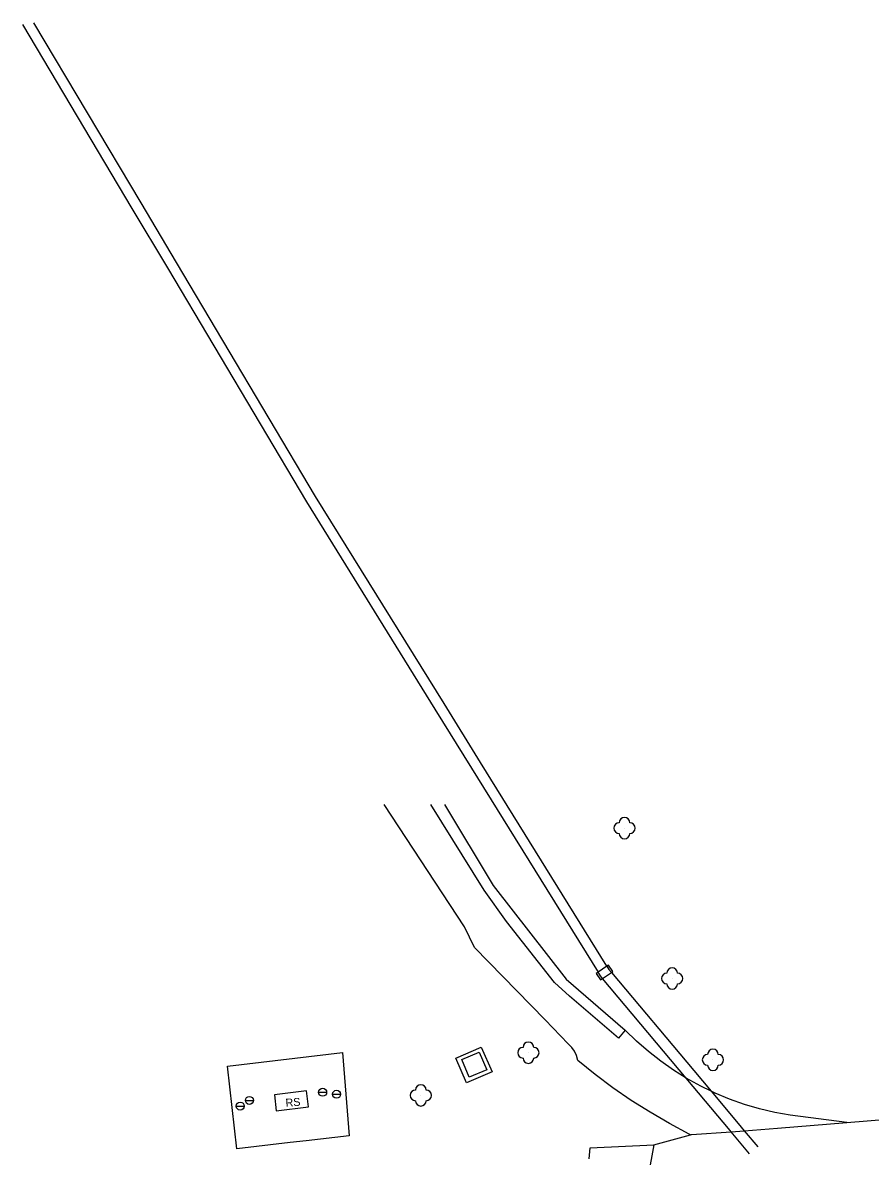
# Model space of a CAD drawing. Extents: x -536391 to -535419, y -1201788 to -1200779.
# Drawn here: x -535812.4 to -535733, y -1201615.3 to -1201509 of the extents above; entities that cross this region are included whole.
import ezdxf

# ---------------------------------------------------------------- set-up
doc = ezdxf.new("R2010")
doc.units = 0
for name, color, linetype in [('CIZÍ_PODZEM_POPIS', 7, 'Continuous'), ('KONEC_VEDENÍ', 7, 'Continuous'), ('POL_ZNAČKA_PRACOVNÍ', 7, 'Continuous'), ('SDEL_EON_POPIS', 7, 'Continuous'), ('TECH_OCHR_PÁSMO_HRAN', 7, 'Continuous')]:
    doc.layers.add(name, color=color, linetype=linetype)

msp = doc.modelspace()

# ---------------------------------------------------------------- linework, layer by layer
at = {"layer": 'CIZÍ_PODZEM_POPIS'}
for p, q in [((-535791.555, -1201610.03), (-535790.805, -1201610.03)), ((-535784.685, -1201609.27), (-535783.935, -1201609.27)), ((-535783.385, -1201609.45), (-535782.635, -1201609.45)), ((-535792.415, -1201610.57), (-535791.665, -1201610.57))]:
    msp.add_line(p, q, dxfattribs=at)
for points in [[(-535792.37, -1201614.57), (-535793.23, -1201606.83), (-535782.45, -1201605.55), (-535781.81, -1201613.35), (-535785.86, -1201613.82), (-535787.35, -1201613.99), (-535792.37, -1201614.57)], [(-535770.81, -1201608.39), (-535771.82, -1201606.08), (-535769.45, -1201605.05), (-535768.43, -1201607.36), (-535770.81, -1201608.39)]]:
    msp.add_lwpolyline(points, dxfattribs=at)
for centre in [(-535784.31, -1201609.27), (-535783.01, -1201609.45), (-535791.18, -1201610.03), (-535792.04, -1201610.57)]:
    msp.add_circle(centre, 0.375, dxfattribs=at)
at = {"layer": 'KONEC_VEDENÍ'}
for centre in [(-535756.01, -1201584.51), (-535751.54, -1201598.61), (-535765.02, -1201605.56), (-535747.71, -1201606.23), (-535775.11, -1201609.56)]:
    msp.add_circle(centre, 0.0005, dxfattribs=at)
for centre, start, end in [((-535756.01, -1201584.01), 0, 179.99999), ((-535756.51, -1201584.51), 89.99999, 269.99999), ((-535755.51, -1201584.51), 270, 89.99999), ((-535756.01, -1201585.01), 179.99999, 359.99999), ((-535752.04, -1201598.61), 89.99999, 269.99999), ((-535751.54, -1201598.11), 0, 179.99999), ((-535751.04, -1201598.61), 270, 89.99999), ((-535751.54, -1201599.11), 179.99999, 359.99999), ((-535765.02, -1201605.06), 0, 179.99999), ((-535765.52, -1201605.56), 89.99999, 269.99999), ((-535764.52, -1201605.56), 270, 89.99999), ((-535748.21, -1201606.23), 89.99999, 269.99999), ((-535747.71, -1201605.73), 0, 179.99999), ((-535747.21, -1201606.23), 270, 89.99999), ((-535765.02, -1201606.06), 179.99999, 359.99999), ((-535747.71, -1201606.73), 179.99999, 359.99999), ((-535775.61, -1201609.56), 89.99999, 269.99999), ((-535775.11, -1201609.06), 0, 179.99999), ((-535774.61, -1201609.56), 270, 89.99999), ((-535775.11, -1201610.06), 179.99999, 359.99999)]:
    msp.add_arc(centre, 0.5, start, end, dxfattribs=at)
at = {"layer": 'SDEL_EON_POPIS'}
msp.add_lwpolyline([(-535785.81, -1201609.15), (-535788.84, -1201609.5), (-535788.67, -1201611), (-535785.63, -1201610.64), (-535785.81, -1201609.15)], dxfattribs=at)
at = {"layer": 'TECH_OCHR_PÁSMO_HRAN'}
for points in [[(-535812.44, -1201509.2), (-535802.19, -1201526.43), (-535798.87, -1201532.01), (-535785.84, -1201553.94), (-535773.78, -1201573.37), (-535770.35, -1201578.89), (-535758.48, -1201598.01)], [(-535757.65, -1201597.46), (-535769.5, -1201578.36), (-535772.93, -1201572.84), (-535784.98, -1201553.42), (-535798.01, -1201531.5), (-535801.33, -1201525.92), (-535811.38, -1201509.02)], [(-535749.81, -1201613.26), (-535749.95, -1201613.19), (-535751.8, -1201612.21), (-535753.6, -1201611.15), (-535755.37, -1201610.03), (-535757.09, -1201608.85), (-535758.76, -1201607.6), (-535760.38, -1201606.28), (-535760.5, -1201605.84), (-535760.7, -1201605.43), (-535760.96, -1201605.06), (-535761.28, -1201604.74), (-535763.44, -1201602.48), (-535770.07, -1201595.7), (-535771.01, -1201593.78), (-535778.54, -1201582.31)], [(-535755.93, -1201603.44), (-535756.58, -1201604.2), (-535761.17, -1201600.26), (-535762.56, -1201598.98), (-535767.08, -1201593.27), (-535769.16, -1201590.33), (-535774.16, -1201582.31)], [(-535772.89, -1201582.31), (-535768.32, -1201589.9), (-535761.47, -1201598.68), (-535755.93, -1201603.44)], [(-535757.22, -1201598.04), (-535757.1, -1201597.96), (-535757.5, -1201597.36), (-535757.65, -1201597.46)], [(-535758.48, -1201598.01), (-535758.66, -1201598.13), (-535758.26, -1201598.73), (-535758.06, -1201598.6)], [(-535757.65, -1201597.46), (-535758.48, -1201598.01)], [(-535758.06, -1201598.6), (-535758.27, -1201598.35), (-535758.48, -1201598.01)], [(-535758.06, -1201598.6), (-535757.22, -1201598.04)], [(-535757.65, -1201597.46), (-535757.47, -1201597.75), (-535757.22, -1201598.04)], [(-535757.22, -1201598.04), (-535749.52, -1201607.23), (-535747.89, -1201609.17)], [(-535750.23, -1201607.94), (-535758.06, -1201598.6)], [(-535750.23, -1201607.94), (-535751.4, -1201607.21), (-535752.61, -1201606.36), (-535753.77, -1201605.45), (-535754.88, -1201604.47), (-535755.93, -1201603.44)], [(-535769.62, -1201605.52), (-535768.93, -1201607.17), (-535770.57, -1201607.87), (-535771.26, -1201606.21), (-535769.62, -1201605.52)], [(-535747.89, -1201609.17), (-535748.85, -1201608.71), (-535750.23, -1201607.94)], [(-535746.02, -1201612.97), (-535746.11, -1201612.86), (-535750.23, -1201607.94)], [(-535735.17, -1201612.12), (-535740.46, -1201611.43), (-535741.92, -1201611.17), (-535743.35, -1201610.83), (-535744.77, -1201610.41), (-535746.16, -1201609.92), (-535747.52, -1201609.35), (-535747.89, -1201609.17)], [(-535747.89, -1201609.17), (-535745.34, -1201612.21), (-535744.78, -1201612.88)], [(-535744.78, -1201612.88), (-535741.67, -1201612.65), (-535735.17, -1201612.12), (-535716.86, -1201610.62)], [(-535753.27, -1201614.2), (-535749.81, -1201613.26)], [(-535749.81, -1201613.26), (-535749.73, -1201613.24), (-535746.02, -1201612.97)], [(-535746.02, -1201612.97), (-535744.78, -1201612.88)], [(-535744.28, -1201615.03), (-535746.02, -1201612.97)], [(-535744.78, -1201612.88), (-535743.51, -1201614.39)], [(-535759.33, -1201615.52), (-535759.23, -1201614.49), (-535753.27, -1201614.2)], [(-535753.27, -1201614.2), (-535754.38, -1201620.36)]]:
    msp.add_lwpolyline(points, dxfattribs=at)

# ---------------------------------------------------------------- texts
at = {"layer": 'POL_ZNAČKA_PRACOVNÍ'}
msp.add_text('RS', height=0.75, rotation=4.78001, dxfattribs=at).set_placement((-535787.76, -1201610.64))

doc.saveas('drawing.dxf')
